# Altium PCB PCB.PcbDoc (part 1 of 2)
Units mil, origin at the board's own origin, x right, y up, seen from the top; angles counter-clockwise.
Board outline 2750 x 2500 mil, 2 copper layers (Top Layer, Bottom Layer), stack 62 mil thick; 49 components, 22 nets, 97 pads, 5 vias.
Unrouted connection lines stored in the file: 2.
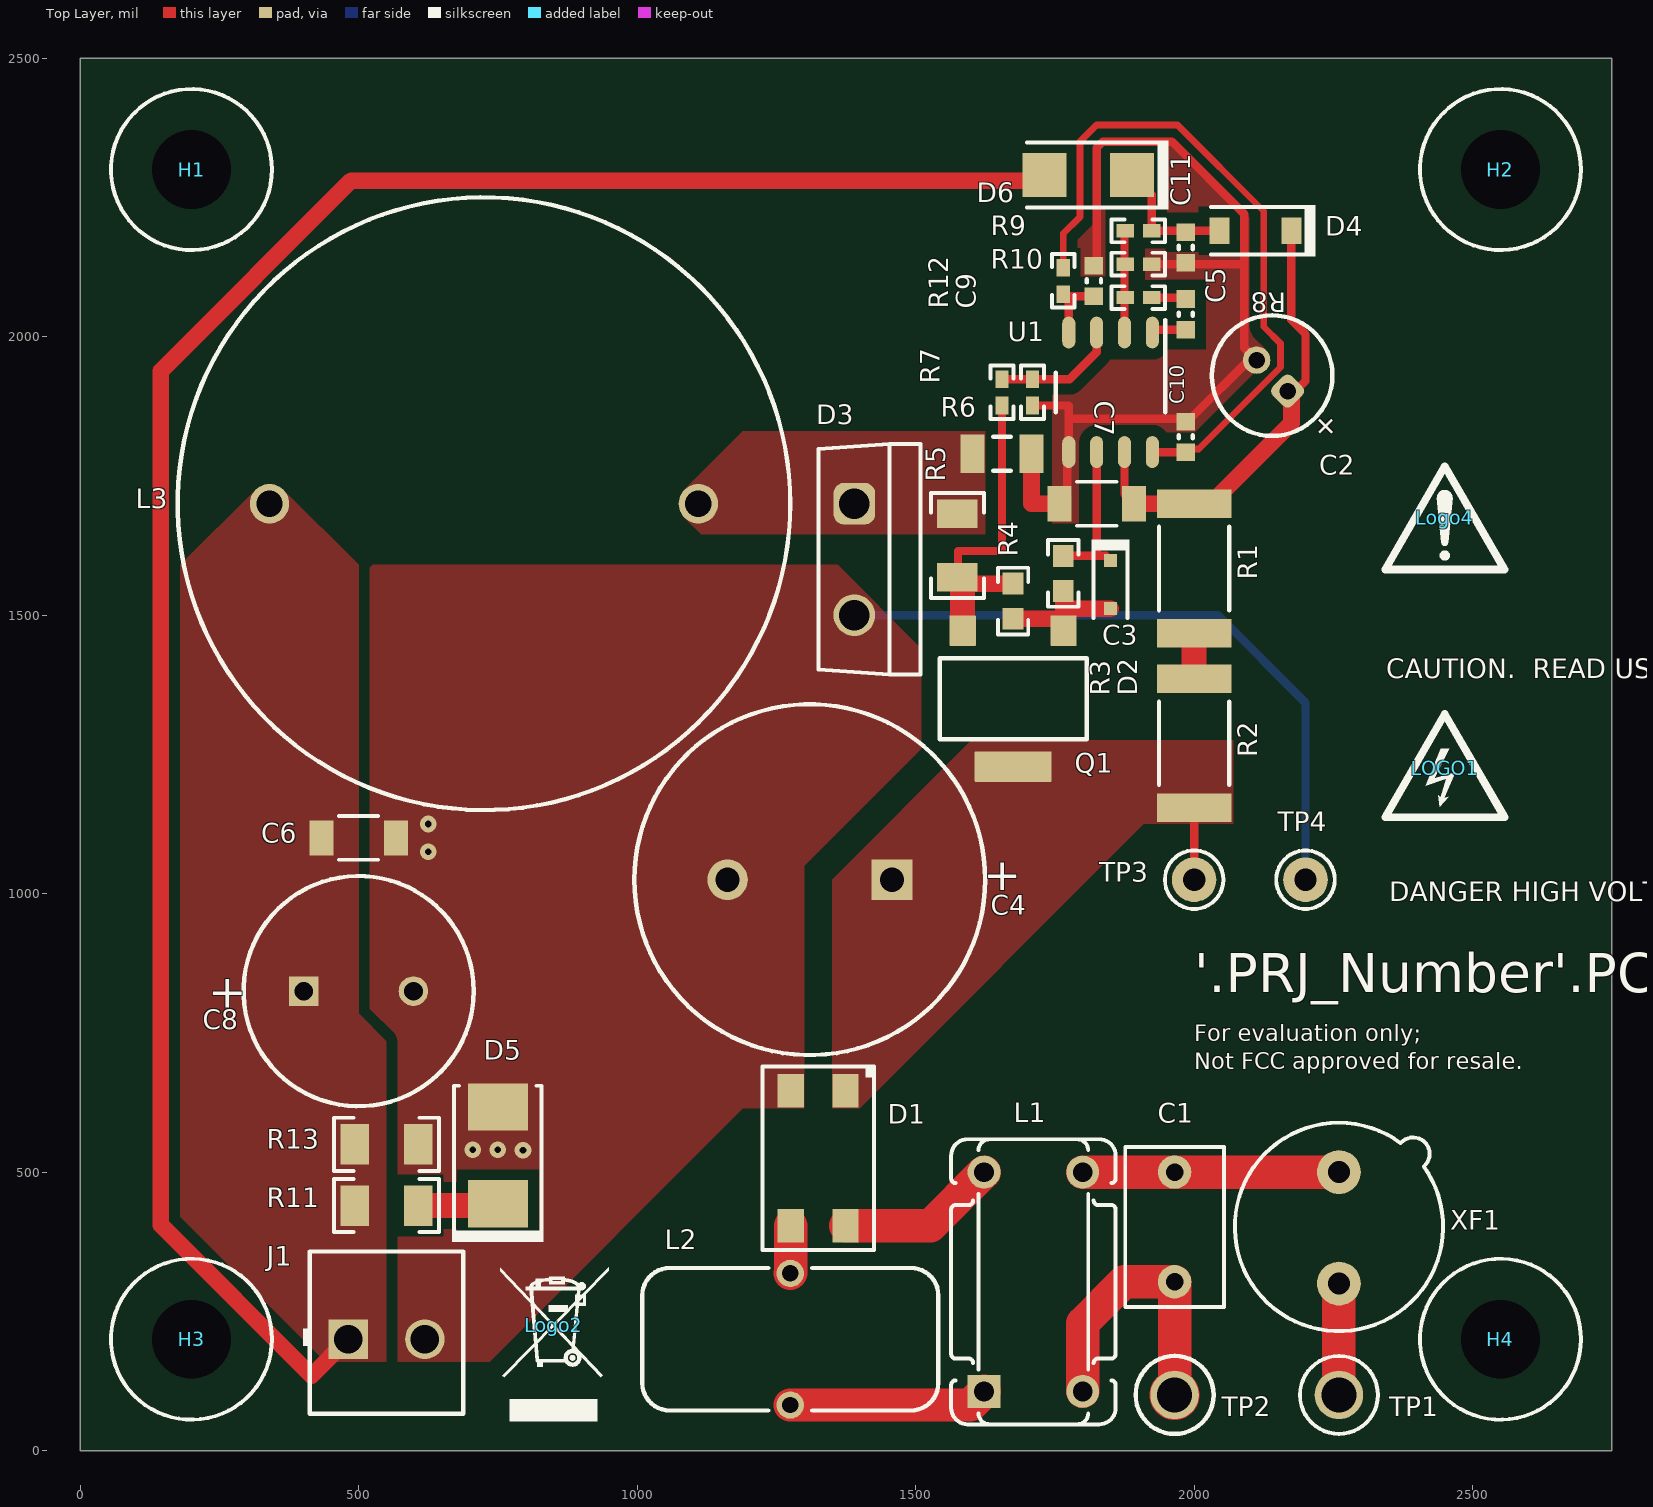
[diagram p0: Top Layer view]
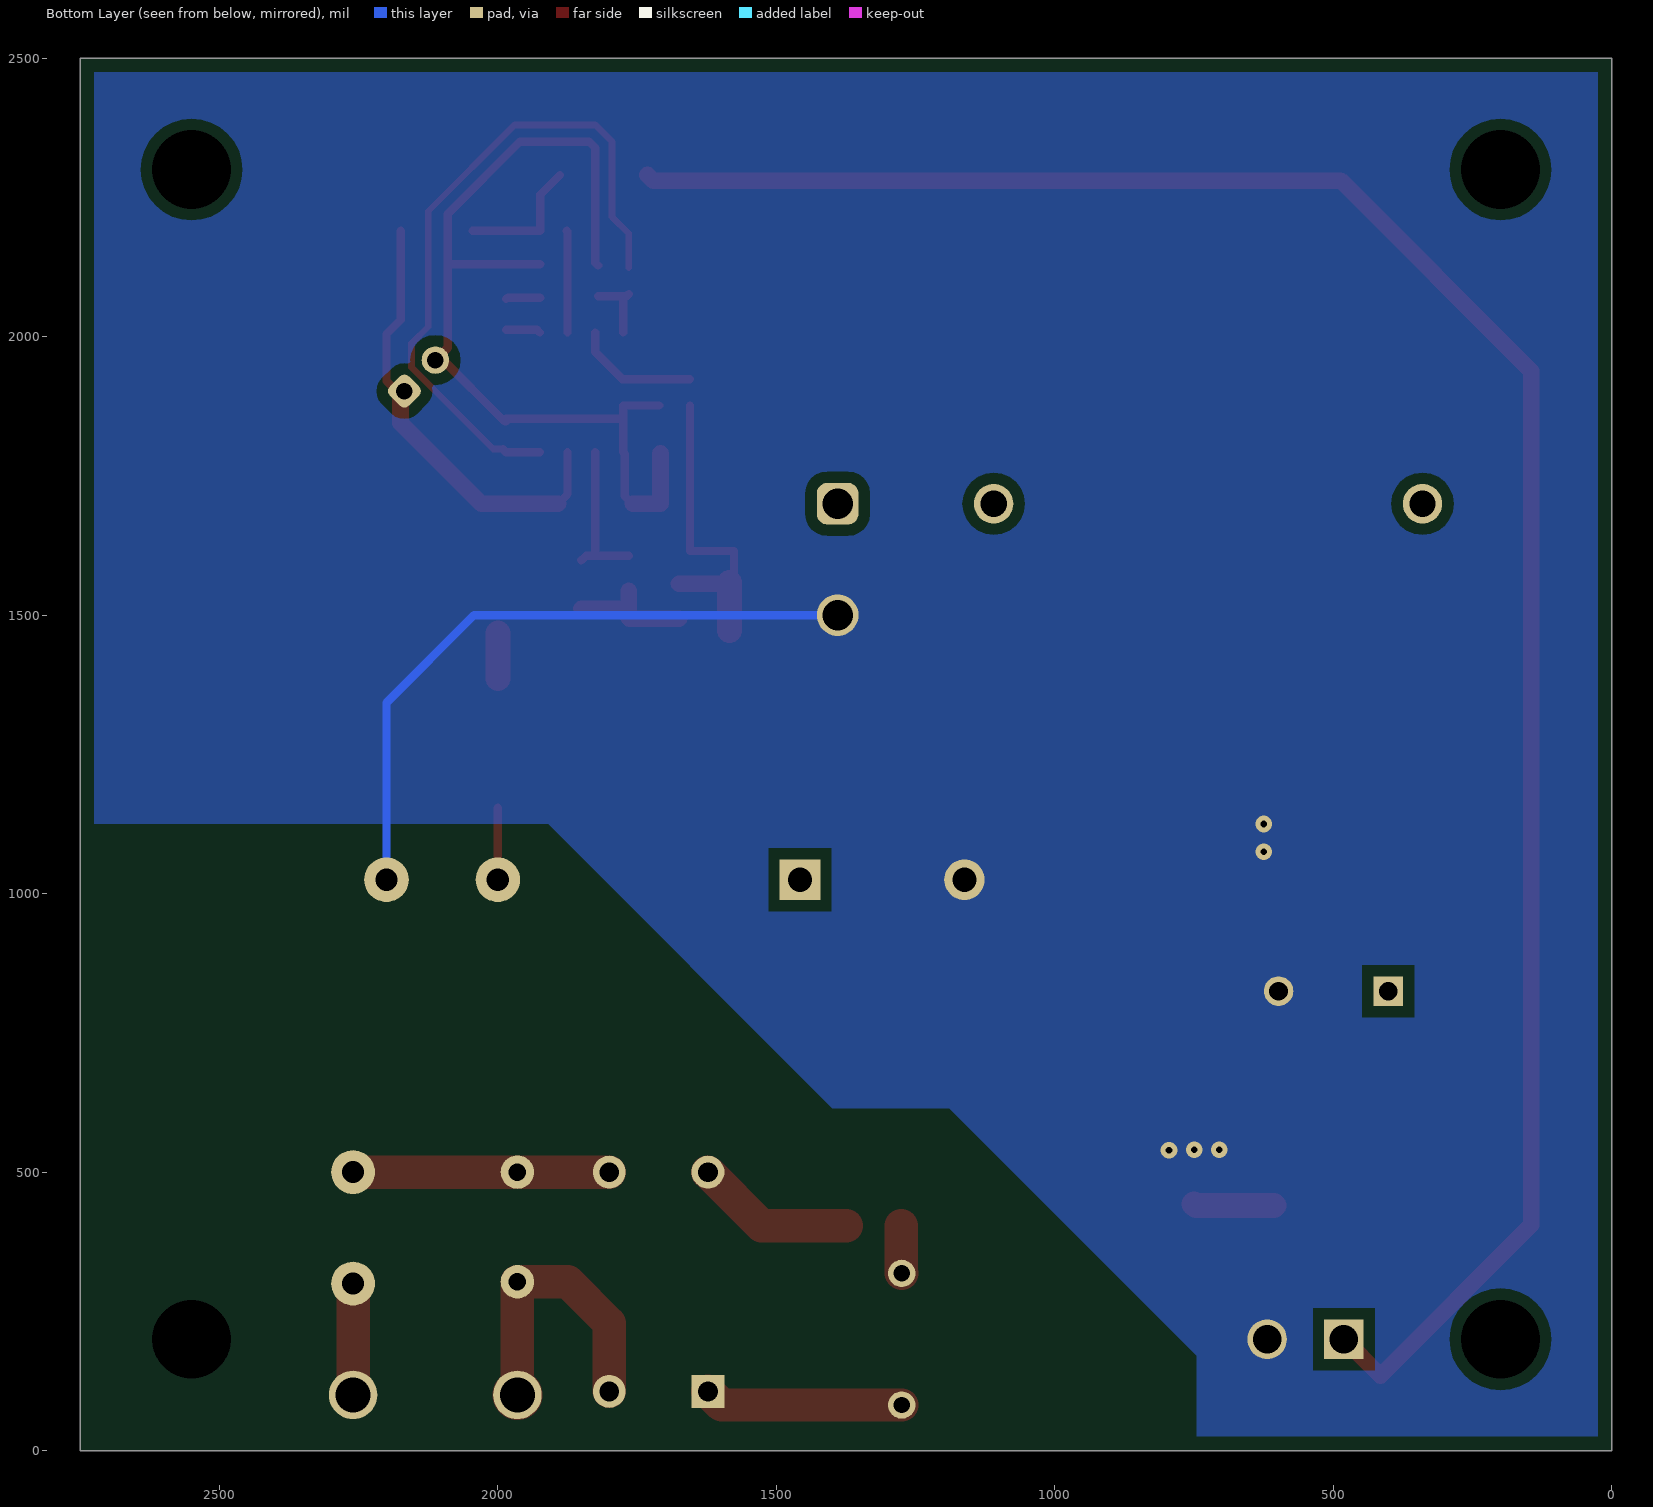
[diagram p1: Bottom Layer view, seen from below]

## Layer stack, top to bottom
Top Solder: solder mask 0.4, Solder Resist, Dk 3.5
Top Layer: signal copper 1.4
Dielectric1: core 59.2, FR-4, Dk 4.8
Bottom Layer: signal copper 1.4
Bottom Solder: solder mask 0.4, Solder Resist, Dk 3.5

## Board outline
0,0 2750,0 2750,2500 0,2500

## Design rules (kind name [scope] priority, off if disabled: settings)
AcuteAngle [All] p1: minimum=4.50000000000000E+0001 checktracksonly=FALSE
AssemblyTestPointUsage [All] p1: valid=2
BoardOutlineClearance BoardOutlineClearance_MountingHoles [OnCopper and InComponentClass('Mounting Holes')] p1: gap=25 ignorepadtopadclearanceinfootprint=FALSE
BoardOutlineClearance BoardOutlineClearance_Poly [OnCopper and InPoly] p2: gap=25 ignorepadtopadclearanceinfootprint=FALSE
BoardOutlineClearance [OnCopper and Not InComponentClass('Logo') and not InComponentClass('FiducialMark') and not InRegion(1000,500,4000,800)] p3: gap=25 ignorepadtopadclearanceinfootprint=FALSE
Clearance Clearance_2 [InNetClass('HV') vs Not InNetClass('HV')] p1: gap=60 ignorepadtopadclearanceinfootprint=FALSE
Clearance Clearance_1 [InNetClass('MV') vs Not InNetClass('MV')] p2: gap=30 ignorepadtopadclearanceinfootprint=FALSE
Clearance Clearance_Keepouts [((IsTrack Or IsArc) And Not InPoly) And IsFree and IsKeepOut vs ((IsTrack Or IsArc) And Not InPoly) And IsFree and IsKeepOut] p3: gap=0 ignorepadtopadclearanceinfootprint=FALSE
Clearance Clearance_BoardEdge_MountingHoles [OnCopper and InComponentClass('Mounting Holes') vs IsKeepOut] p4: gap=40 ignorepadtopadclearanceinfootprint=FALSE except(0: Arc-Hole Track-Hole SMDPad-Hole THPad-Hole Via-Hole Fill-Hole Poly-Hole Region-Hole Text-Hole)
Clearance Clearance_BoardEdge_Poly [OnCopper and InPoly vs IsKeepOut] p5: gap=50 ignorepadtopadclearanceinfootprint=FALSE except(0: Arc-Hole Track-Hole SMDPad-Hole THPad-Hole Via-Hole Fill-Hole Poly-Hole Region-Hole Text-Hole)
Clearance Clearance_BoardEdge [OnCopper and Not InComponentClass('Logo') and not InComponentClass('FiducialMark') and not InRegion(1000,500,4000,800) and Not IsKeepout vs IsKeepOut] p6: gap=50 ignorepadtopadclearanceinfootprint=FALSE
Clearance Clearance_Poly [InPolygon] p7: gap=20 ignorepadtopadclearanceinfootprint=FALSE except(0: Arc-Hole Track-Hole SMDPad-Hole THPad-Hole Via-Hole Fill-Hole Poly-Hole Region-Hole Text-Hole)
Clearance [All] p8: gap=7.87 ignorepadtopadclearanceinfootprint=FALSE except(0: Arc-Hole Track-Hole SMDPad-Hole THPad-Hole Via-Hole Fill-Hole Poly-Hole Region-Hole Text-Hole)
ComponentClearance ComponentClearance_MountingHoles_FiducialMarks [InComponentClass('Mounting Holes') vs InComponentClass('FiducialMark')] p1: gap=20 collisioncheckmode=3 verticalgap=10 showdistances=FALSE
ComponentClearance ComponentClearance_Shunt [InComponentClass('Header') vs InComponentClass('Shunt')] p2: gap=0 collisioncheckmode=3 verticalgap=0 showdistances=FALSE
ComponentClearance ComponentClearance_Logo [InComponentClass('Logo')] p3: gap=5 collisioncheckmode=3 verticalgap=10 showdistances=FALSE
ComponentClearance ComponentClearance_ScrewToNut [(HasFootprint('NY PMS 440 0025 PH')) vs (HasFootprint('Keystone_1902C'))] p4: gap=20 collisioncheckmode=3 verticalgap=100000 showdistances=FALSE
ComponentClearance ComponentClearance_MountingHoles [InComponentClass('Mounting Holes')] p5: gap=20 collisioncheckmode=3 verticalgap=10 showdistances=FALSE
ComponentClearance ComponentClearance_SmallPassives [HasFootprint('0201*') or HasFootprint('0402*') or HasFootprint('0508') or HasFootprint('0603*') or HasFootprint('0612') or HasFootprint('0805*') or HasFootprint('0815*') or HasFootprint('0830*') or HasFootprint('1206*') or HasFootprint('1210*') or HasFootprint('1808*') or HasFootprint('1812*') or HasFootprint('1825*') or HasFootprint('2010*') or HasFootprint('2220*') or HasFootprint('2225*') or HasFootprint('2512*') or HasFootprint('2728*') or HasFootprint('3518*') vs HasFootprint('0201*') or HasFootprint('0402*') or HasFootprint('0508') or HasFootprint('0603*') or HasFootprint('0612') or HasFootprint('0805*') or HasFootprint('0815*') or HasFootprint('0830*') or HasFootprint('1206*') or HasFootprint('1210*') or HasFootprint('1808*') or HasFootprint('1812*') or HasFootprint('1825*') or HasFootprint('2010*') or HasFootprint('2220*') or HasFootprint('2225*') or HasFootprint('2512*') or HasFootprint('2728*') or HasFootprint('3518*')] p6: gap=20 collisioncheckmode=3 verticalgap=20 showdistances=FALSE
ComponentClearance ComponentClearance_THtoSMT [IsThruComponent vs IsSMTComponent] p7: gap=10 collisioncheckmode=3 verticalgap=10 showdistances=FALSE
ComponentClearance ComponentClearance_THtoTH [IsThruComponent vs IsThruComponent] p8: gap=10 collisioncheckmode=3 verticalgap=10 showdistances=FALSE
ComponentClearance [All] p9: gap=10 collisioncheckmode=3 verticalgap=10 showdistances=FALSE
DiffPairsRouting [All] p1: maxlimit=100 minlimit=10 mostfreqgap=10 toplayer_minwidth=15 toplayer_maxwidth=15 toplayer_prefwidth=15 bottomlayer_minwidth=15 bottomlayer_maxwidth=15 bottomlayer_prefwidth=15 maxuncoupledlength=1000
FabricationTestPointUsage TestPointUsage [All] p1: valid=2 allowmultiple=FALSE
FabricationTestpoint Testpoint [All] p1: side=3 testpointundercomponent=TRUE minsize=40 maxsize=100 preferedsize=60 minholesize=0 maxholesize=40 preferedholesize=32 testpointgrid=1 allowsidetop=TRUE allowsidebottom=TRUE usegrid=TRUE gridtolerance=0.01
FanoutControl Fanout_LCC [IsLCC] p1: bgadir=Out bgaviamode=Centered fanoutstyle=Auto fanoutdirection=Alternating viagrid=1 // Fanout_LCC (Default Rule)
FanoutControl Fanout_BGA [IsBGA] p2: bgadir=Out bgaviamode=Centered fanoutstyle=Auto fanoutdirection=Alternating viagrid=1 // Fanout_BGA (Default Rule)
FanoutControl Fanout_Default [All] p4: bgadir=Out bgaviamode=Centered fanoutstyle=Auto fanoutdirection=Alternating viagrid=1 // Fanout_Default (Default Rule)
FanoutControl Fanout_Small [(CompPinCount < 5)] p5: bgadir=Out bgaviamode=Centered fanoutstyle=Auto fanoutdirection=OutThenIn viagrid=1 // Fanout_Small (Default Rule)
Height [All] p1: minheight=0 maxheight=3000 prefheight=500
HoleSize [All] p1: absolutevalues=TRUE maxlimit=251 minlimit=7.87 maxpercent=80.000 minpercent=20.000
MinimumAnnularRing MinimumAnnularRing_ThermalPadVias [IsVia and InAnyComponent] p1: minimumring=5.91
MinimumAnnularRing [All] p2: minimumring=8
MinimumSolderMaskSliver MinimumSolderMaskSliver_Logo [InComponentClass('Logo') vs InComponentClass('Logo')] p1: minsoldermaskwidth=0.7
MinimumSolderMaskSliver [All] p2: minsoldermaskwidth=3.94
PlaneConnect [All] p1: planeconnectstyle=Direct reliefexpansion=10 reliefentries=4 reliefconductorwidth=10 reliefairgap=10
PolygonConnect PolygonConnect_15 [All vs IsNamedPolygon('C109_2') Or  IsNamedPolygon('C107_2') Or  IsNamedPolygon('HV') Or  IsNamedPolygon('Q203_5') Or  IsNamedPolygon('C107_2') Or  IsNamedPolygon('HS') Or  IsNamedPolygon('Q201_5') Or  IsNamedPolygon('Q203_5') Or  IsNamedPolygon('C106_2') Or  IsNamedPolygon('C108_2') Or  IsNamedPolygon('Vout') Or  IsNamedPolygon('Q203_5') Or  IsNamedPolygon('C108_2') Or  IsNamedPolygon('C113_2') Or  IsNamedPolygon('Q203_5') Or  IsNamedPolygon('Q201_5') Or  IsNamedPolygon('C107_2') Or  IsNamedPolygon('C102_1') Or  IsNamedPolygon('SGND') Or  IsNamedPolygon('GND') Or  IsNamedPolygon('SGND') Or  IsNamedPolygon('GND') Or  IsNamedPolygon('IN+') Or  IsNamedPolygon('IN+') Or  IsNamedPolygon('Q201_5') Or  IsNamedPolygon('Q201_5') Or  IsNamedPolygon('SGND') Or  IsNamedPolygon('SGND') Or  IsNamedPolygon('Vout') Or  IsNamedPolygon('Vout') Or  IsNamedPolygon('IN+') Or  IsNamedPolygon('GND') Or  IsNamedPolygon('IN+') Or  IsNamedPolygon('GND')] p1: connectstyle=Direct reliefconductorwidth=10 reliefentries=4 polygonreliefangle="90 Angle" airgapwidth=10
PolygonConnect PolygonConnect_14 [All vs IsNamedPolygon('C106_2') Or  IsNamedPolygon('C107_2') Or  IsNamedPolygon('C107_2') Or  IsNamedPolygon('C107_2') Or  IsNamedPolygon('C102_1') Or  IsNamedPolygon('Q203_5') Or  IsNamedPolygon('Vout') Or  IsNamedPolygon('Q203_5') Or  IsNamedPolygon('Q203_5') Or  IsNamedPolygon('Q201_5') Or  IsNamedPolygon('C108_2') Or  IsNamedPolygon('Q203_5') Or  IsNamedPolygon('HS') Or  IsNamedPolygon('HV') Or  IsNamedPolygon('C108_2') Or  IsNamedPolygon('Q201_5') Or  IsNamedPolygon('C109_2') Or  IsNamedPolygon('Q201_5') Or  IsNamedPolygon('Q201_5') Or  IsNamedPolygon('C113_2')] p2: connectstyle=Direct reliefconductorwidth=10 reliefentries=4 polygonreliefangle="90 Angle" airgapwidth=10
PolygonConnect PolygonConnect_13 [All vs IsNamedPolygon('C102_1') Or  IsNamedPolygon('HV') Or  IsNamedPolygon('C107_2') Or  IsNamedPolygon('C109_2') Or  IsNamedPolygon('C107_2') Or  IsNamedPolygon('C108_2') Or  IsNamedPolygon('C106_2') Or  IsNamedPolygon('C108_2') Or  IsNamedPolygon('C113_2') Or  IsNamedPolygon('C107_2')] p3: connectstyle=Direct reliefconductorwidth=10 reliefentries=4 polygonreliefangle="90 Angle" airgapwidth=10
PolygonConnect PolygonConnect_12 [All vs IsNamedPolygon('C107_2') Or  IsNamedPolygon('C113_2') Or  IsNamedPolygon('C106_2') Or  IsNamedPolygon('C107_2') Or  IsNamedPolygon('C107_2') Or  IsNamedPolygon('C102_1')] p4: connectstyle=Direct reliefconductorwidth=10 reliefentries=4 polygonreliefangle="90 Angle" airgapwidth=10
PolygonConnect PolygonConnect_11 [All vs IsNamedPolygon('C106_2') Or  IsNamedPolygon('C102_1') Or  IsNamedPolygon('C107_2') Or  IsNamedPolygon('C107_2') Or  IsNamedPolygon('C107_2')] p5: connectstyle=Direct reliefconductorwidth=10 reliefentries=4 polygonreliefangle="90 Angle" airgapwidth=10
PolygonConnect PolygonConnect_10 [All vs IsNamedPolygon('C106_2')] p6: connectstyle=Direct reliefconductorwidth=10 reliefentries=4 polygonreliefangle="90 Angle" airgapwidth=10
PolygonConnect PolygonConnect_9 [All vs IsNamedPolygon('C11_1') Or  IsNamedPolygon('Vin') Or  IsNamedPolygon('Vin') Or  IsNamedPolygon('5V') Or  IsNamedPolygon('D6_2') Or  IsNamedPolygon('Q3_3') Or  IsNamedPolygon('GND2') Or  IsNamedPolygon('GND2') Or  IsNamedPolygon('GND') Or  IsNamedPolygon('Q3_4') Or  IsNamedPolygon('12V5') Or  IsNamedPolygon('GND') Or  IsNamedPolygon('12V5') Or  IsNamedPolygon('D3_1')] p7: connectstyle=Direct reliefconductorwidth=10 reliefentries=4 polygonreliefangle="90 Angle" airgapwidth=10
PolygonConnect PolygonConnect_8 [All vs IsNamedPolygon('C11_1') Or  IsNamedPolygon('Vin') Or  IsNamedPolygon('12V5') Or  IsNamedPolygon('Q3_3') Or  IsNamedPolygon('GND2') Or  IsNamedPolygon('GND2') Or  IsNamedPolygon('5V') Or  IsNamedPolygon('Q3_4') Or  IsNamedPolygon('12V5')] p8: connectstyle=Direct reliefconductorwidth=10 reliefentries=4 polygonreliefangle="90 Angle" airgapwidth=10
PolygonConnect PolygonConnect_7 [All vs IsNamedPolygon('GND2') Or  IsNamedPolygon('GND2') Or  IsNamedPolygon('5V') Or  IsNamedPolygon('12V5') Or  IsNamedPolygon('12V5') Or  IsNamedPolygon('C11_1')] p9: connectstyle=Direct reliefconductorwidth=10 reliefentries=4 polygonreliefangle="90 Angle" airgapwidth=10
PolygonConnect PolygonConnect_6 [All vs IsNamedPolygon('GND2') Or  IsNamedPolygon('SGND') Or  IsNamedPolygon('GND1') Or  IsNamedPolygon('C901_1') Or  IsNamedPolygon('SGND') Or  IsNamedPolygon('GND2') Or  IsNamedPolygon('GND1')] p10: connectstyle=Direct reliefconductorwidth=10 reliefentries=4 polygonreliefangle="90 Angle" airgapwidth=10
PolygonConnect PolygonConnect_5 [All vs IsNamedPolygon('GND1') Or  IsNamedPolygon('GND1')] p11: connectstyle=Direct reliefconductorwidth=10 reliefentries=4 polygonreliefangle="90 Angle" airgapwidth=10
PolygonConnect PolygonConnect_4 [All vs IsNamedPolygon('C21_1') Or  IsNamedPolygon('C5_1') Or  IsNamedPolygon('C12_2') Or  IsNamedPolygon('C2_2') Or  IsNamedPolygon('C13_1') Or  IsNamedPolygon('C28_1') Or  IsNamedPolygon('C6_1') Or  IsNamedPolygon('GND') Or  IsNamedPolygon('GND2') Or  IsNamedPolygon('C14_1') Or  IsNamedPolygon('C13_1') Or  IsNamedPolygon('Q1_3') Or  IsNamedPolygon('C14_1') Or  IsNamedPolygon('C5_1') Or  IsNamedPolygon('GND2') Or  IsNamedPolygon('C28_1') Or  IsNamedPolygon('D5_2') Or  IsNamedPolygon('D6_2') Or  IsNamedPolygon('D2_1') Or  IsNamedPolygon('C12_2') Or  IsNamedPolygon('D2_1') Or  IsNamedPolygon('C4_1') Or  IsNamedPolygon('C4_1') Or  IsNamedPolygon('C2_2') Or  IsNamedPolygon('GND') Or  IsNamedPolygon('C33_1') Or  IsNamedPolygon('C9_1')] p12: connectstyle=Direct reliefconductorwidth=10 reliefentries=4 polygonreliefangle="90 Angle" airgapwidth=10
PolygonConnect PolygonConnect_3 [All vs IsNamedPolygon('C28_1') Or  IsNamedPolygon('C12_2') Or  IsNamedPolygon('C28_1') Or  IsNamedPolygon('C9_1') Or  IsNamedPolygon('D5_2') Or  IsNamedPolygon('C12_2') Or  IsNamedPolygon('C2_2') Or  IsNamedPolygon('C14_1') Or  IsNamedPolygon('C4_1') Or  IsNamedPolygon('C14_1') Or  IsNamedPolygon('D6_2') Or  IsNamedPolygon('GND2') Or  IsNamedPolygon('Q1_3') Or  IsNamedPolygon('C5_1') Or  IsNamedPolygon('D2_1') Or  IsNamedPolygon('C4_1') Or  IsNamedPolygon('C13_1') Or  IsNamedPolygon('C5_1') Or  IsNamedPolygon('C13_1') Or  IsNamedPolygon('C33_1') Or  IsNamedPolygon('D2_1') Or  IsNamedPolygon('GND') Or  IsNamedPolygon('GND') Or  IsNamedPolygon('GND2') Or  IsNamedPolygon('C2_2') Or  IsNamedPolygon('C6_1') Or  IsNamedPolygon('C21_1')] p13: connectstyle=Direct reliefconductorwidth=10 reliefentries=4 polygonreliefangle="90 Angle" airgapwidth=10
PolygonConnect PolygonConnect_2 [All vs IsNamedPolygon('C21_1') Or  IsNamedPolygon('C4_1') Or  IsNamedPolygon('D5_2') Or  IsNamedPolygon('C5_1') Or  IsNamedPolygon('C14_1') Or  IsNamedPolygon('C13_1') Or  IsNamedPolygon('C4_1') Or  IsNamedPolygon('C33_1') Or  IsNamedPolygon('C12_2') Or  IsNamedPolygon('D2_1') Or  IsNamedPolygon('C2_2') Or  IsNamedPolygon('C28_1') Or  IsNamedPolygon('C12_2') Or  IsNamedPolygon('D2_1') Or  IsNamedPolygon('C5_1') Or  IsNamedPolygon('Q1_3') Or  IsNamedPolygon('GND') Or  IsNamedPolygon('D6_2') Or  IsNamedPolygon('C6_1') Or  IsNamedPolygon('C2_2') Or  IsNamedPolygon('C14_1') Or  IsNamedPolygon('C28_1') Or  IsNamedPolygon('C13_1') Or  IsNamedPolygon('C9_1') Or  IsNamedPolygon('GND')] p14: connectstyle=Direct reliefconductorwidth=10 reliefentries=4 polygonreliefangle="90 Angle" airgapwidth=10
PolygonConnect PolygonConnect_1 [All vs IsNamedPolygon('C28_1') Or  IsNamedPolygon('D5_2') Or  IsNamedPolygon('C5_1') Or  IsNamedPolygon('C5_1') Or  IsNamedPolygon('D2_1') Or  IsNamedPolygon('C21_1') Or  IsNamedPolygon('C9_1') Or  IsNamedPolygon('C4_1') Or  IsNamedPolygon('C14_1') Or  IsNamedPolygon('C28_1') Or  IsNamedPolygon('C6_1') Or  IsNamedPolygon('C12_2') Or  IsNamedPolygon('C33_1') Or  IsNamedPolygon('C4_1') Or  IsNamedPolygon('C13_1') Or  IsNamedPolygon('C12_2') Or  IsNamedPolygon('D6_2') Or  IsNamedPolygon('C2_2') Or  IsNamedPolygon('C14_1') Or  IsNamedPolygon('D2_1') Or  IsNamedPolygon('C2_2') Or  IsNamedPolygon('C13_1')] p15: connectstyle=Direct reliefconductorwidth=10 reliefentries=4 polygonreliefangle="90 Angle" airgapwidth=10
PolygonConnect [All] p16: connectstyle=Direct reliefconductorwidth=10 reliefentries=4 polygonreliefangle="90 Angle" airgapwidth=10
RoutingVias ThermalPadVias [IsVia and InAnyComponent] p1: holewidth=7.87 width=19.68 viastyle="Through Hole" minholewidth=7.87 minwidth=19.68 maxholewidth=12.99 maxwidth=23.62
RoutingVias [All] p2: holewidth=16 width=34 viastyle="Through Hole" minholewidth=7.87 minwidth=20 maxholewidth=40 maxwidth=65
SilkToBoardRegionClearance [Not ((IsComment or IsDesignator) And (Hide <> 'False')) and not InRegion(1000,500,4000,800)] p1:
SilkToSilkClearance SilkToSilkClearance_Pb-FreeLogo [(HasFootprint('Pb-Free_Overlay_Medium') OR HasFootprint('Pb-Free_Overlay_Small')) vs (HasFootprint('Pb-Free_Overlay_Medium') OR HasFootprint('Pb-Free_Overlay_Small'))] p1: silktosilkclearance=0
SilkToSilkClearance [All] p2: silktosilkclearance=4
SilkToSolderMaskClearance SilkToComponentPadClearance [IsPad and InAnycomponent] p1: minsilkscreentomaskgap=5 clearancetoexposedcopper=TRUE
SilkToSolderMaskClearance "Silk to Solder Mask Opening" [All] p2: minsilkscreentomaskgap=4 clearancetoexposedcopper=FALSE
SolderMaskExpansion [All] p1: expansion=1.97
Width [All] p1: maxlimit=100 minlimit=6 preferedwidth=10 checkconnectedcopper=TRUE
14 further rules are at their usual default settings.

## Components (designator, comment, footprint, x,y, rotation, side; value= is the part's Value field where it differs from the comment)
C1 "B32529C3104K" B32529_450x950x730 1965,401.57 r270 top value=0.1uF
C2 "UVR1E220MDD6TP" VR_500X1100 2140,1930 r135 top value=22uF
C3 "GRM31CR71H225KA88L" 1206_180 1825,1700 r180 top value=2.2uF
C4 "EEUED2E470S" CAPPR7.5-16x20 1310,1025 r180 top value=47uF
C5 "GRM188R71E224KA88D" 0603L 1985,2040 r90 top value=0.22uF
C6 "GRM31CR71H225KA88L" 1206_180 500,1100 r0 top value=2.2uF
C7 "GRM1555C1H101JA01D" 0402 1710,1900 r90 top value=100pF
C8 "UHW1V471MPD" HW_1000x1600 500,825 r0 top value=470uF
C9 "GRM188R71E102KA01D" 0603L 1820,2100 r90 top value=1000pF
C10 "GRM188R71E105KA12D" 0603L 1985,1820 r90 top value=1uF
C11 "GRM188R71E224KA88D" 0603L 1985,2160 r270 top value=0.22uF
D1 "HD04-T" MiniDIP 1325,524.99 r270 top value=400V
D2 "MMDL914-TP" SOD-323 1850,1555 r270 top value=100V
D3 "LQA30T300" TO-220AC 1390,1600 r270 top value=300V
D4 "1N4148W-7-F" SOD-123 2110,2190 r180 top value=100V
D5 "SMBJ24A-13-F" SMB 750,530 r90 top value=24V
D6 "ES1JTR" SMA 1810,2290 r180 top value=600V
H1 "4820" KEYSTONE_4820 200,2300 r0 top
H2 "4820" KEYSTONE_4820 2550,2300 r0 top
H3 "4820" KEYSTONE_4820 200,200 r0 top
H4 "4820" KEYSTONE_4820 2550,200 r0 top
J1 "691214110002" Wurth_691214110002 550,200 r0 top
L1 "744821150" WE-CMB_XS 1711.42,303.15 r90 top value=5mH
L2 "7447031" WE-FI_1350x700 1275,199.99 r90 top value=140uH
L3 "1130-471K-RC" 1130-471K 725,1700 r180 top value=470uH
LOGO1 "DANGER HIGH VOLTAGE" IEC_HighVoltage_Small 2450,1225 r0 top
Logo2 "WEEE logo" WEEE_Minimum 850,225 r0 top
Logo3 "FCC disclaimer" FCC_disclaimer 6075,500 r0 top
Logo4 "CAUTION.  READ USER GUIDE BEFORE USE" IEC_Caution_Small 2450,1675 r0 top
Q1 "IPN60R360P7SATMA1" FP-IPN60R360P7SATMA1_SOT223-MFG 1675,1350 r270 top
R1 "Resistor" 2512 2000,1583.86 r90 top value=330k
R2 "Resistor" 2512 2000,1270 r90 top value=330k
R3 "CRCW060310R0FKEA" 0603 1765,1575 r90 top value=10.0
R4 "CRCW0603100KFKEA" 0603 1675,1525 r90 top value=100k
R5 "CSR1206FTR620" 1206 1575,1625 r90 top value=0.62
R6 "CRCW12060000Z0EA" 1206L 1655,1790 r0 top value=0
R7 "CRCW0402511RFKED" 0402 1655,1900 r90 top value=511
R8 "CRCW040249K9FKED" 0402 1900,2070 r180 top value=49.9k
R9 "CRCW040222K1FKED" 0402 1900,2190 r0 top value=22.1k
R10 "CRCW04022K49FKED" 0402 1900,2130 r180 top value=2.49k
R11 "Resistor" 1206 550,440 r180 top value=10.0
R12 "CRCW040241K2FKED" 0402 1765,2100 r90 top value=41.2k
R13 "Resistor" 1206 550,550 r180 top value=5.1k
TP1 "5125" Keystone5125 2260,100 r180 top
TP2 "5127" Keystone5127 1965,99.99 r270 top
TP3 "5000" Keystone5000 2000,1025 r90 top
TP4 "5001" Keystone5001 2200,1025 r90 top
U1 "TL2842BDR-8" D0008A_N 1850,1900 r270 top
XF1 "56000001009" FuseHolder_560000010 2260,400 r90 top value=TR5

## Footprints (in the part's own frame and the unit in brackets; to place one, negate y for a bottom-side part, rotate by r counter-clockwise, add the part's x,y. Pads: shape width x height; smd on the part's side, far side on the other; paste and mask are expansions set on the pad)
0402 [mm] "0402 from SM-752 data"
  rect 0.8x0.6 smd: 1(-0.6,0) 2(0.6,0)
  silkscreen extent -1.22,-0.52 1.22,0.52, body extent -0.55,-0.3 0.55,0.3, height 0.6
0603 [mm] "0603 from SM-752 data"
  rect 1x0.95 smd: 1(-0.8,0) 2(0.8,0)
  silkscreen extent -1.52,-0.69 1.52,0.69, body extent -0.87,-0.47 0.87,0.47, height 1
0603L [mm] "0603 from SM-752 data"
  rect 0.8x0.85 smd: 1(-0.7,0) 2(0.7,0)
  silkscreen extent -0.07,-0.33 0.07,0.33, body extent -0.87,-0.47 0.87,0.47, height 1
1130-471K [mm] "TH, 2-Leads, Dia 1100mil, Pin Spacing 770mil"
  round 1.8 hole 1.2: 1(-9.779,0) 2(9.779,0)
  silkscreen extent -13.97,-13.97 13.97,13.97, body extent -13.97,-13.97 13.97,13.97, height 21.34
1206 [mm] "1206 from SM-752 data"
  rect 1.3x1.85 smd: 1(-1.45,0) 2(1.45,0)
  silkscreen extent -2.4,-1.21 2.4,1.21, body extent -1.7,-0.9 1.7,0.9, height 1.35
1206_180 [mm] "1206_180"
  rect 1.1x1.6 smd: 1(-1.7,0) 2(1.7,0)
  silkscreen extent -0.9,-1 0.9,1, body extent -1.75,-0.95 1.75,0.95, height 1.8
1206L [mm] "1206 from SM-752 data"
  rect 1.1x1.75 smd: 1(-1.35,0) 2(1.35,0)
  silkscreen extent -0.4,-0.77 0.4,0.77, body extent -1.7,-0.9 1.7,0.9, height 1.35
2512 [mm] "Chip Resistor, Body 6.3x3.2mm, IPC Medium Density"
  rect 1.3x3.4 smd: 1(-2.95,0) 2(2.95,0)
  silkscreen extent -1.9,-1.6 1.9,1.6, body extent -3.22,-1.67 3.22,1.67, height 0.71
B32529_450x950x730 [mil] "EPCOS"
  round 60 hole 31: 1(-98.43,0) 2(98.43,0)
  silkscreen extent -144,-89 144,89, body extent -144,-89 144,89, height 374
CAPPR7.5-16x20 [mm] "Capacitor, Electrolytic, Radial; Body 16 x 20 mm (Dia.xH typ); Pin Spacing 7.5 mm (typ)"
  rect 1.85x1.85 hole 1.1: 1(-3.75,0)
  round 1.85 hole 1.1: 2(3.75,0)
  silkscreen extent -8,-8 8,8, body extent -8,-8.01 8,8.01, height 22
D0008A_N [mm] "SOIC, 8-Leads, Body 4.9x3.9mm, Pitch 1.27mm, IPC Medium Density"
  oval 1.45x0.6 smd: 1(-2.725,1.905) 2(-2.725,0.635) 3(-2.725,-0.635) 4(-2.725,-1.905) 5(2.725,-1.905) 6(2.725,-0.635) 7(2.725,0.635) 8(2.725,1.905)
  silkscreen extent -3.3,-2.5 0.9,2.5, body extent -3,-2.45 3,2.45, height 1.63
FCC_disclaimer [mil]
FP-IPN60R360P7SATMA1_SOT223-MFG [mm]
  rrect8% 1.4x1.2 smd paste+0 mask+0: 1(-3.1,2.3) 3(-3.1,-2.3)
  rrect7% 1.4x3.5 smd paste+0 mask+0: 2(3.1,0)
  silkscreen extent -1.85,-3.35 1.85,3.35, body extent -3.9,-3.6 3.9,3.6, height 0.25
FuseHolder_560000010 [mm] "Littelfuse fuse holder TR5"
  round 2 hole 1: 1(-2.54,0) 2(2.54,0)
  silkscreen extent -4.71,-4.75 4.79,4.75, body extent -4.75,-4.74 4.75,4.75, height 5.6
HW_1000x1600 [mm] "TH, 2-Leads, Dia 10mm, Pin Spacing 5mm"
  rect 1.35x1.35 hole 0.85: 1(-2.5,0)
  round 1.35 hole 0.85: 2(2.5,0)
  silkscreen extent -5.25,-5.25 5.25,5.25, body extent -5.25,-5.25 5.26,5.25, height 17.51
IEC_Caution_Small [mil]
  silkscreen extent -107,-93 107,92
IEC_HighVoltage_Small [mil]
  silkscreen extent -107,-88 107,97
Keystone5000 [mil] "For Keystone 500x miniature loop terminals"
  round 80 hole 40: 1(0,0)
  silkscreen extent -52,-52 52,52, body extent -49,-49 49,49, height 182
Keystone5001 [mil] "For Keystone 500x miniature loop terminals"
  round 80 hole 40: 1(0,0)
  silkscreen extent -52,-52 52,52, body extent -49,-49 49,49, height 182
Keystone5125 [mil] "Keystone Multipurpose loops"
  round 87 hole 63: 1(0,0)
  silkscreen extent -70,-70 70,70, body extent -63,-63 63,62, height 319
Keystone5127 [mil] "Keystone Multipurpose loops"
  round 87 hole 63: 1(0,0)
  silkscreen extent -70,-70 70,70, body extent -63,-63 63,62, height 319
KEYSTONE_4820 [mm] "HEX NYLON STANDOFF 6-32, M-F 1\""
  round 0.025 on Mech3: 0(0,0)
  round 1 hole 3.6 unplated: MH(0,0)
  silkscreen extent -3.67,-3.67 3.67,3.67, body extent -3.67,-3.17 3.67,3.18, height 25.42
MiniDIP [mm] "Land pattern created based on STEP model."
  rect 1.52x1.2 smd: 1(-3.075,1.25) 2(-3.075,-1.25) 3(3.075,-1.25) 4(3.075,1.25)
  silkscreen extent -4.19,-2.54 4.19,2.54, body extent -3.5,-2.45 3.5,2.45, height 2.75
SMA [mm] "Molded Diode, 2-Leads, Body 4.3x2.6mm, IPC Medium Density, based on OnSemi component dimensions and land pattern"
  rect 2x2 smd: 1(-2,0) 2(2,0)
  silkscreen extent -3.66,-1.57 2.79,1.57, body extent -2.6,-1.3 2.6,1.3, height 2.42
SMB [mil] "Molded Diode, 2-Leads, Body 5.4x3.6mm, IPC Medium Density, based on OnSemi component dimensions"
  rect 85x107.99 smd: 1(-87.01,0) 2(87.01,0)
  silkscreen extent -155,-82 125,82, body extent -106,-71 106,71, height 91
SOD-123 [mm] "On Semi recommended land pattern"
  rect 0.915x1.22 smd: 1(-1.637,0) 2(1.637,0)
  silkscreen extent -2.74,-1.17 2.03,1.17, body extent -1.93,-0.9 1.93,0.9, height 1.35
SOD-323 [mm] "NXP recommended land pattern"
  rect 0.6x0.6 smd paste-0.05: 1(-1.1,0) 2(1.1,0)
  silkscreen extent -2.06,-0.86 1.53,0.86, body extent -1.3,-0.67 1.3,0.68, height 1.1
TO-220AC [mm]
  rrect50% 1.9x1.9 hole 1.4: 1(-2.54,0)
  round 1.9 hole 1.4: 3(2.54,0)
  silkscreen extent -5.25,-1.64 5.26,3.01, body extent -5.25,-1.64 5.26,3.01, height 19.09
VR_500X1100 [mm] "TH, 2-Leads, Dia 5mm, Pin Spacing 2mm"
  rrect50% 1.25x1.25 hole 0.75: 1(-1,0)
  round 1.25 hole 0.75: 2(1,0)
  silkscreen extent -2.75,-2.75 2.75,2.75, body extent -2.75,-2.75 2.75,2.75, height 12.51
WE-CMB_XS [mm] "WE-CMB Series Size XS"
  rect 1.5x1.5 hole 0.9: 1(-5,2.25)
  round 1.5 hole 0.9: 2(-5,-2.25) 3(5,-2.25) 4(5,2.25)
  silkscreen extent -6.5,-3.75 6.5,3.75, body extent -6.5,-3.75 6.5,3.75, height 16.24
WE-FI_1350x700 [mm] "TH, 2-Leads, Dia 13.5mm"
  round 1.25 hole 0.75: 1(-3,0) 2(3,0)
  silkscreen extent -3.25,-6.75 3.25,6.75, body extent -3.25,-6.75 3.25,6.75, height 13.32
WEEE_Minimum [mil] "WEEElie bin"
  silkscreen extent -95,-172 99,104
Wurth_691214110002 [mm] "Receptacle, 3.5mm, 2x1, TH"
  rect 1.8x1.8 hole 1.3: 1(-1.75,0)
  round 1.8 hole 1.3: 2(1.75,0)
  silkscreen extent -3.8,-3.4 3.5,4, body extent -3.9,-3.4 3.5,4, height 8.5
